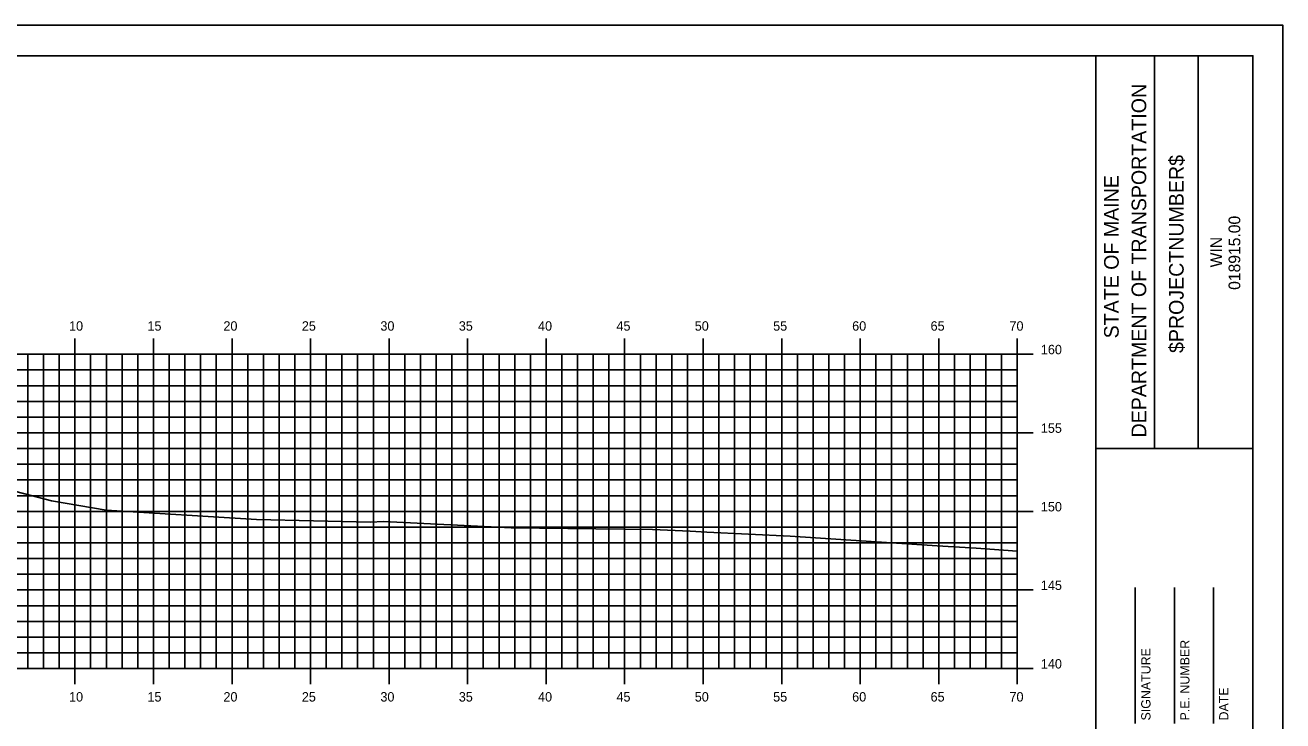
# Model space of a CAD drawing. Extents: x 850752 to 850923, y 365876 to 365986.
# Drawn here: x 850841.5 to 850921.5, y 365941.5 to 365985.8 of the extents above; entities that cross this region are included whole.
import ezdxf

# ---------------------------------------------------------------- set-up
doc = ezdxf.new("R2010")
doc.units = 0
for name, color, linetype in [('BORDER', 7, 'Continuous'), ('H_V ANNOTATION', 7, 'Continuous'), ('MAJOR', 7, 'Continuous'), ('MINOR', 7, 'Continuous'), ('PLOT BOUNDARY', 7, 'Continuous'), ('S_Roadway_Centerline', 7, 'Continuous')]:
    doc.layers.add(name, color=color, linetype=linetype)

msp = doc.modelspace()

# ---------------------------------------------------------------- linework, layer by layer
at = {"layer": 'BORDER'}
for p, q in [((850909.629, 365878.833), (850909.629, 365983.833)), ((850913.358, 365958.83), (850913.358, 365983.83)), ((850916.153, 365958.83), (850916.153, 365983.83)), ((850909.63, 365958.827), (850919.629, 365958.827)), ((850912.129, 365941.336), (850912.129, 365949.984)), ((850914.629, 365941.336), (850914.629, 365949.984)), ((850917.129, 365941.336), (850917.129, 365949.984))]:
    msp.add_line(p, q, dxfattribs=at)
msp.add_lwpolyline([(850759.629, 365878.833), (850919.629, 365878.833), (850919.629, 365983.833), (850759.629, 365983.833)], close=True, dxfattribs=at)
at = {"layer": 'MAJOR'}
for p, q in [((850844.629, 365965.835), (850844.629, 365964.833)), ((850849.629, 365965.835), (850849.629, 365964.833)), ((850854.629, 365965.835), (850854.629, 365964.833)), ((850859.629, 365965.835), (850859.629, 365964.833)), ((850864.629, 365965.835), (850864.629, 365964.833)), ((850869.629, 365965.835), (850869.629, 365964.833)), ((850874.629, 365965.835), (850874.629, 365964.833)), ((850879.629, 365965.835), (850879.629, 365964.833)), ((850884.629, 365965.835), (850884.629, 365964.833)), ((850889.629, 365965.835), (850889.629, 365964.833)), ((850894.629, 365965.835), (850894.629, 365964.833)), ((850899.629, 365965.835), (850899.629, 365964.833)), ((850904.629, 365965.835), (850904.629, 365964.833)), ((850764.629, 365964.833), (850904.629, 365964.833)), ((850764.629, 365964.833), (850904.629, 365964.833)), ((850844.629, 365944.833), (850844.629, 365964.833)), ((850849.629, 365944.833), (850849.629, 365964.833)), ((850854.629, 365944.833), (850854.629, 365964.833)), ((850859.629, 365944.833), (850859.629, 365964.833)), ((850864.629, 365944.833), (850864.629, 365964.833)), ((850869.629, 365944.833), (850869.629, 365964.833)), ((850874.629, 365944.833), (850874.629, 365964.833)), ((850879.629, 365944.833), (850879.629, 365964.833)), ((850884.629, 365944.833), (850884.629, 365964.833)), ((850889.629, 365944.833), (850889.629, 365964.833)), ((850894.629, 365944.833), (850894.629, 365964.833)), ((850899.629, 365944.833), (850899.629, 365964.833)), ((850905.631, 365964.833), (850903.627, 365964.833)), ((850904.629, 365944.833), (850904.629, 365964.833)), ((850904.629, 365944.833), (850904.629, 365964.833)), ((850764.629, 365959.833), (850904.629, 365959.833)), ((850905.631, 365959.833), (850903.627, 365959.833)), ((850764.629, 365954.833), (850904.629, 365954.833)), ((850905.631, 365954.833), (850903.627, 365954.833)), ((850764.629, 365949.833), (850904.629, 365949.833)), ((850905.631, 365949.833), (850903.627, 365949.833)), ((850764.629, 365944.833), (850904.629, 365944.833)), ((850764.629, 365944.833), (850904.629, 365944.833)), ((850844.629, 365943.831), (850844.629, 365944.833)), ((850849.629, 365943.831), (850849.629, 365944.833)), ((850854.629, 365943.831), (850854.629, 365944.833)), ((850859.629, 365943.831), (850859.629, 365944.833)), ((850864.629, 365943.831), (850864.629, 365944.833)), ((850869.629, 365943.831), (850869.629, 365944.833)), ((850874.629, 365943.831), (850874.629, 365944.833)), ((850879.629, 365943.831), (850879.629, 365944.833)), ((850884.629, 365943.831), (850884.629, 365944.833)), ((850889.629, 365943.831), (850889.629, 365944.833)), ((850894.629, 365943.831), (850894.629, 365944.833)), ((850899.629, 365943.831), (850899.629, 365944.833)), ((850905.631, 365944.833), (850903.627, 365944.833)), ((850904.629, 365943.831), (850904.629, 365944.833))]:
    msp.add_line(p, q, dxfattribs=at)
at = {"layer": 'MINOR'}
for p, q in [((850841.629, 365944.833), (850841.629, 365964.833)), ((850842.629, 365944.833), (850842.629, 365964.833)), ((850843.629, 365944.833), (850843.629, 365964.833)), ((850845.629, 365944.833), (850845.629, 365964.833)), ((850846.629, 365944.833), (850846.629, 365964.833)), ((850847.629, 365944.833), (850847.629, 365964.833)), ((850848.629, 365944.833), (850848.629, 365964.833)), ((850850.629, 365944.833), (850850.629, 365964.833)), ((850851.629, 365944.833), (850851.629, 365964.833)), ((850852.629, 365944.833), (850852.629, 365964.833)), ((850853.629, 365944.833), (850853.629, 365964.833)), ((850855.629, 365944.833), (850855.629, 365964.833)), ((850856.629, 365944.833), (850856.629, 365964.833)), ((850857.629, 365944.833), (850857.629, 365964.833)), ((850858.629, 365944.833), (850858.629, 365964.833)), ((850860.629, 365944.833), (850860.629, 365964.833)), ((850861.629, 365944.833), (850861.629, 365964.833)), ((850862.629, 365944.833), (850862.629, 365964.833)), ((850863.629, 365944.833), (850863.629, 365964.833)), ((850865.629, 365944.833), (850865.629, 365964.833)), ((850866.629, 365944.833), (850866.629, 365964.833)), ((850867.629, 365944.833), (850867.629, 365964.833)), ((850868.629, 365944.833), (850868.629, 365964.833)), ((850870.629, 365944.833), (850870.629, 365964.833)), ((850871.629, 365944.833), (850871.629, 365964.833)), ((850872.629, 365944.833), (850872.629, 365964.833)), ((850873.629, 365944.833), (850873.629, 365964.833)), ((850875.629, 365944.833), (850875.629, 365964.833)), ((850876.629, 365944.833), (850876.629, 365964.833)), ((850877.629, 365944.833), (850877.629, 365964.833)), ((850878.629, 365944.833), (850878.629, 365964.833)), ((850880.629, 365944.833), (850880.629, 365964.833)), ((850881.629, 365944.833), (850881.629, 365964.833)), ((850882.629, 365944.833), (850882.629, 365964.833)), ((850883.629, 365944.833), (850883.629, 365964.833)), ((850885.629, 365944.833), (850885.629, 365964.833)), ((850886.629, 365944.833), (850886.629, 365964.833)), ((850887.629, 365944.833), (850887.629, 365964.833)), ((850888.629, 365944.833), (850888.629, 365964.833)), ((850890.629, 365944.833), (850890.629, 365964.833)), ((850891.629, 365944.833), (850891.629, 365964.833)), ((850892.629, 365944.833), (850892.629, 365964.833)), ((850893.629, 365944.833), (850893.629, 365964.833)), ((850895.629, 365944.833), (850895.629, 365964.833)), ((850896.629, 365944.833), (850896.629, 365964.833)), ((850897.629, 365944.833), (850897.629, 365964.833)), ((850898.629, 365944.833), (850898.629, 365964.833)), ((850900.629, 365944.833), (850900.629, 365964.833)), ((850901.629, 365944.833), (850901.629, 365964.833)), ((850902.629, 365944.833), (850902.629, 365964.833)), ((850903.629, 365944.833), (850903.629, 365964.833)), ((850764.629, 365963.833), (850904.629, 365963.833)), ((850904.629, 365963.833), (850903.627, 365963.833)), ((850764.629, 365962.833), (850904.629, 365962.833)), ((850904.629, 365962.833), (850903.627, 365962.833)), ((850764.629, 365961.833), (850904.629, 365961.833)), ((850904.629, 365961.833), (850903.627, 365961.833)), ((850764.629, 365960.833), (850904.629, 365960.833)), ((850904.629, 365960.833), (850903.627, 365960.833)), ((850764.629, 365958.833), (850904.629, 365958.833)), ((850904.629, 365958.833), (850903.627, 365958.833)), ((850764.629, 365957.833), (850904.629, 365957.833)), ((850904.629, 365957.833), (850903.627, 365957.833)), ((850764.629, 365956.833), (850904.629, 365956.833)), ((850904.629, 365956.833), (850903.627, 365956.833)), ((850764.629, 365955.833), (850904.629, 365955.833)), ((850904.629, 365955.833), (850903.627, 365955.833)), ((850764.629, 365953.833), (850904.629, 365953.833)), ((850904.629, 365953.833), (850903.627, 365953.833)), ((850764.629, 365952.833), (850904.629, 365952.833)), ((850904.629, 365952.833), (850903.627, 365952.833)), ((850764.629, 365951.833), (850904.629, 365951.833)), ((850904.629, 365951.833), (850903.627, 365951.833)), ((850764.629, 365950.833), (850904.629, 365950.833)), ((850904.629, 365950.833), (850903.627, 365950.833)), ((850764.629, 365948.833), (850904.629, 365948.833)), ((850904.629, 365948.833), (850903.627, 365948.833)), ((850764.629, 365947.833), (850904.629, 365947.833)), ((850904.629, 365947.833), (850903.627, 365947.833)), ((850764.629, 365946.833), (850904.629, 365946.833)), ((850904.629, 365946.833), (850903.627, 365946.833)), ((850764.629, 365945.833), (850904.629, 365945.833)), ((850904.629, 365945.833), (850903.627, 365945.833))]:
    msp.add_line(p, q, dxfattribs=at)
at = {"layer": 'PLOT BOUNDARY'}
msp.add_lwpolyline([(850751.536, 365875.774), (850921.536, 365875.774), (850921.536, 365985.774), (850751.536, 365985.774)], close=True, dxfattribs=at)
at = {"layer": 'S_Roadway_Centerline'}
msp.add_lwpolyline([(850840.868, 365956.102), (850843.133, 365955.511), (850846.61, 365954.903), (850856.188, 365954.314), (850863.443, 365954.157), (850864.277, 365954.189), (850872.394, 365953.778), (850881.396, 365953.689), (850883.804, 365953.566), (850884.868, 365953.522), (850890.164, 365953.257), (850899.531, 365952.646), (850902.012, 365952.483), (850904.629, 365952.301)], dxfattribs=at)

# ---------------------------------------------------------------- texts
at = {"layer": 'BORDER'}
for s, height, p in [('DEPARTMENT OF TRANSPORTATION', 0.93176, (850912.836, 365959.539)), ('$PROJECTNUMBER$', 0.93176, (850915.221, 365964.912)), ('STATE OF MAINE', 0.93176, (850911.084, 365965.845)), ('018915.00', 0.7453, (850918.825, 365968.931)), ('WIN', 0.7453, (850917.666, 365970.363)), ('SIGNATURE', 0.5906, (850913.109, 365941.528)), ('P.E. NUMBER', 0.59055, (850915.59, 365941.528)), ('DATE', 0.5906, (850918.07, 365941.528))]:
    msp.add_text(s, height=height, rotation=90, dxfattribs=at).set_placement(p)
at = {"layer": 'H_V ANNOTATION'}
for s, p in [('10', (850844.254, 365966.333)), ('15', (850849.246, 365966.333)), ('20', (850854.083, 365966.333)), ('25', (850859.075, 365966.333)), ('30', (850864.077, 365966.333)), ('35', (850869.069, 365966.333)), ('40', (850874.115, 365966.333)), ('45', (850879.107, 365966.333)), ('50', (850884.093, 365966.333)), ('55', (850889.085, 365966.333)), ('60', (850894.115, 365966.333)), ('65', (850899.107, 365966.333)), ('70', (850904.131, 365966.333)), ('160', (850906.129, 365964.833)), ('155', (850906.129, 365959.833)), ('150', (850906.129, 365954.833)), ('145', (850906.129, 365949.833)), ('140', (850906.129, 365944.833)), ('10', (850844.254, 365942.733)), ('15', (850849.246, 365942.733)), ('20', (850854.083, 365942.733)), ('25', (850859.075, 365942.733)), ('30', (850864.077, 365942.733)), ('35', (850869.069, 365942.733)), ('40', (850874.115, 365942.733)), ('45', (850879.107, 365942.733)), ('50', (850884.093, 365942.733)), ('55', (850889.085, 365942.733)), ('60', (850894.115, 365942.733)), ('65', (850899.107, 365942.733)), ('70', (850904.131, 365942.733))]:
    msp.add_text(s, height=0.6, dxfattribs=at).set_placement(p)

doc.saveas('drawing.dxf')
